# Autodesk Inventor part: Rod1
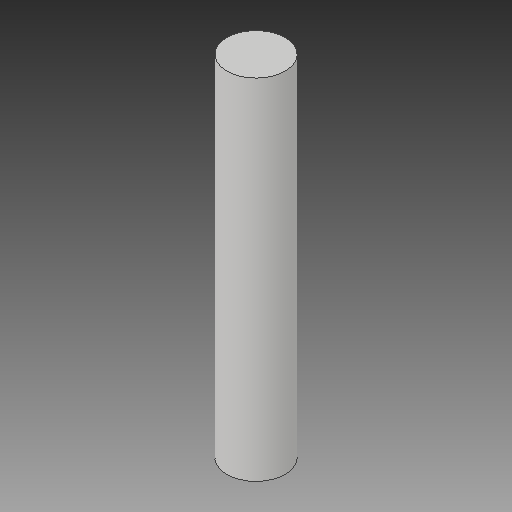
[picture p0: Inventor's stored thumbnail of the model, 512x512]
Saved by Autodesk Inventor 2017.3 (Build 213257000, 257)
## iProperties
Created: 2020-03
Part Number: Rod1
Material: Generic
Document SubType Name: Modeling
Designer: Tim_G
Density: 1 g/cm^3
Appearance: Default
Author: Tim_G
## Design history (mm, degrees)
sketch "Sketch1"
  geometry: C1 r 2.5 at (0, 0); 1 further point
  constraints: 1 centre point, 1 coincident
  dimensions: "d0" = 5 diameter of C1
extrude "Extrusion1" new body sketch "Sketch1" distance "d1" = 30; taper "d2" = 0 deg
body "Solid1"
